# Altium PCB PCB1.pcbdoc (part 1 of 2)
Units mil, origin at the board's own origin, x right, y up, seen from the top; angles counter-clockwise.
Board outline 4280 x 3470 mil, 2 copper layers (Top Layer, Bottom Layer); 101 components, 68 nets, 325 pads, 717 vias.
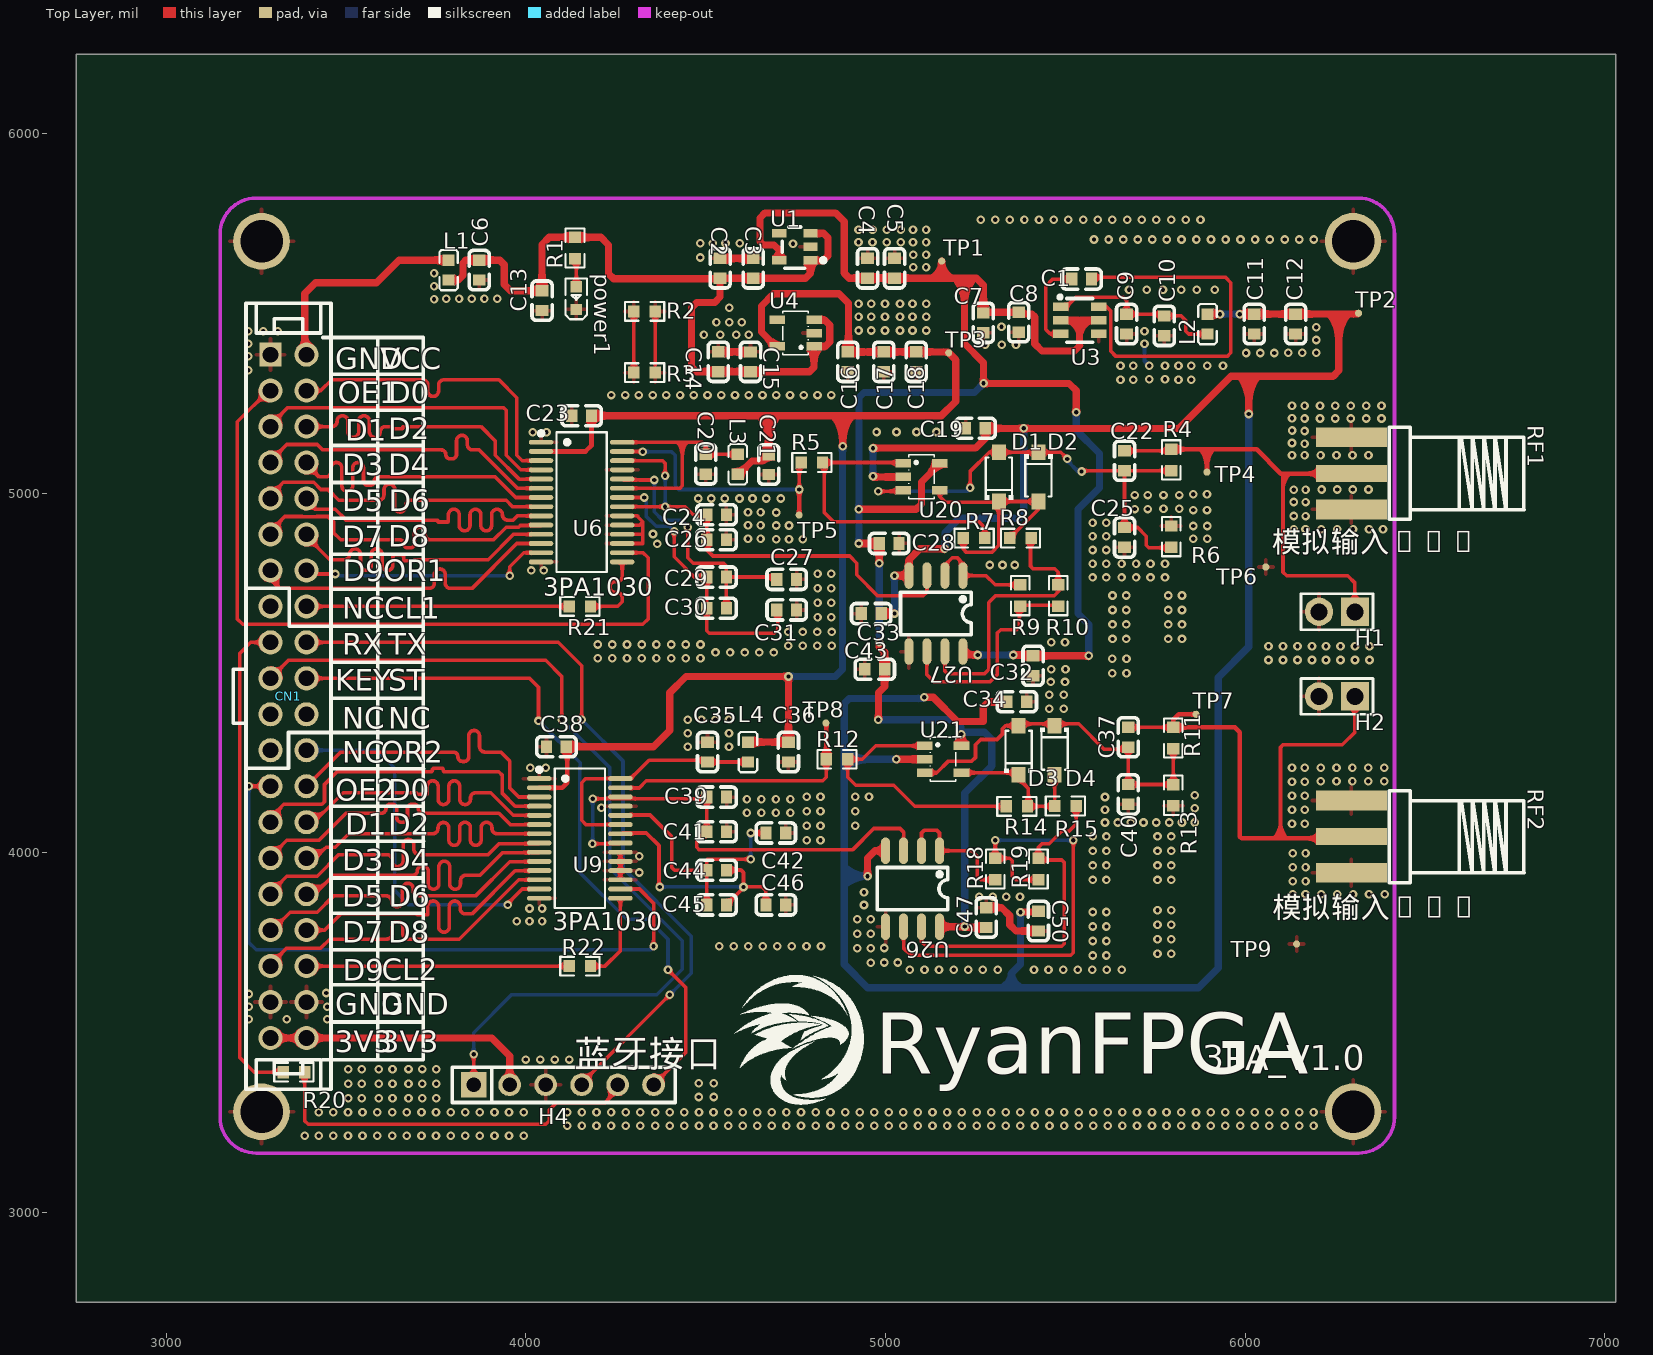
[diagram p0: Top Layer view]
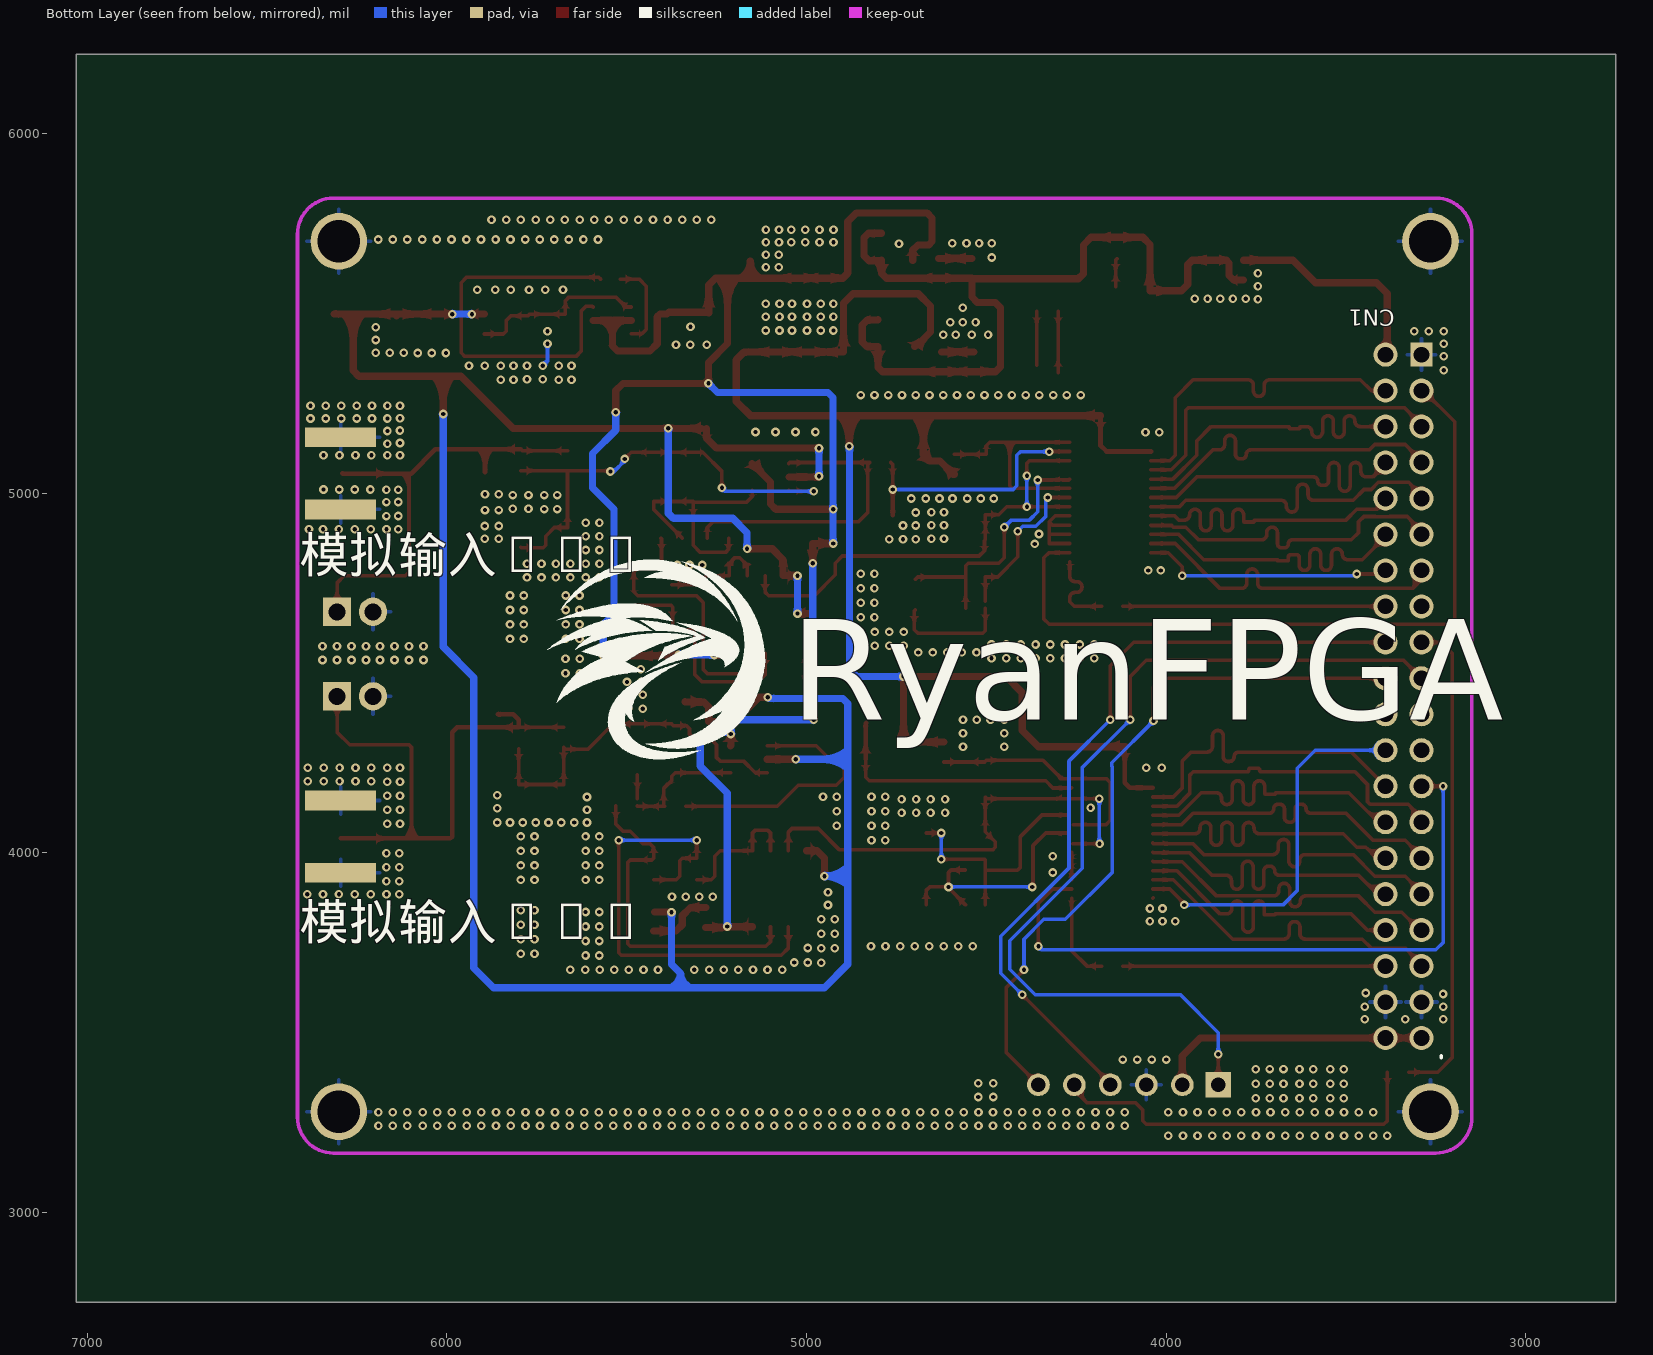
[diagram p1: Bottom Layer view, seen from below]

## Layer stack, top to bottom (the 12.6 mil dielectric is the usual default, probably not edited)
Top Layer: signal copper (thickness not stored)
Dielectric: dielectric 12.6, FR-4, Dk 4.8
Bottom Layer: signal copper (thickness not stored)

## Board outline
7030,2750 2750,2750 2750,6220 7030,6220

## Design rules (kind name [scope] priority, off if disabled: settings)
BoardOutlineClearance copperThickness1oz [All] p0: genericclearance=10 ignorepadtopadclearanceinfootprint=FALSE except(0: Arc-SplitContinuation Track-SplitContinuation SMDPad-SplitContinuation THPad-SplitContinuation Via-SplitContinuation Fill-SplitContinuation Poly-SplitContinuation Region-SplitContinuation Text-SplitContinuation; 6: Track-CutoutEdge SMDPad-CutoutEdge THPad-CutoutEdge Via-CutoutEdge Region-CutoutEdge; 11.8: Track-OutlineEdge SMDPad-OutlineEdge THPad-OutlineEdge Via-OutlineEdge Fill-OutlineEdge Region-OutlineEdge Poly-OutlineEdge Text-OutlineEdge Fill-CutoutEdge)
BoardOutlineClearance copperThickness2oz [All] p0: genericclearance=10 ignorepadtopadclearanceinfootprint=FALSE except(0: Arc-SplitContinuation Track-SplitContinuation SMDPad-SplitContinuation THPad-SplitContinuation Via-SplitContinuation Fill-SplitContinuation Poly-SplitContinuation Region-SplitContinuation Text-SplitContinuation; 6: Track-CutoutEdge SMDPad-CutoutEdge THPad-CutoutEdge Via-CutoutEdge Region-CutoutEdge; 11.8: Track-OutlineEdge SMDPad-OutlineEdge THPad-OutlineEdge Via-OutlineEdge Fill-OutlineEdge Region-OutlineEdge Poly-OutlineEdge Text-OutlineEdge Fill-CutoutEdge)
Clearance copperThickness1oz [(InNet('$1N10336') OR InNet('$1N10331') OR InNet('VCC_5V') OR InNet('AGND') OR InNet('VCC+') OR InNet('$1N10485') OR InNet('VCC-') OR InNet('VCC') OR InNet('$1N3540') OR InNet('$1N1392') OR InNet('$1N17421') OR InNet('$1N3888') OR InNet('$1N3734') OR InNet('$1N12630') OR InNet('$1N12612') OR InNet('$1N17460') OR InNet('$1N12628') OR InNet('$1N12635') OR InNet('$1N12634') OR InNet('$1N2309') OR InNet('$1N12618') OR InNet('VCC_IN') OR InNet('$1N11129') OR InNet('$1N3290') OR InNet('$1N3284') OR InNet('$1N2656') OR InNet('$1N12627') OR InNet('$1N12626') OR InNet('$1N12621') OR InNet('AD2_D0') OR InNet('AD2_CLK') OR InNet('AD2_D2') OR InNet('AD2_D1') OR InNet('AD2_D4') OR InNet('AD2_D3') OR InNet('AD2_D6') OR InNet('AD2_D5') OR InNet('AD2_D8') OR InNet('AD2_D7') OR InNet('AD2_OE') OR InNet('AD2_D9') OR InNet('AD1_OE') OR InNet('AD2_OTR') OR InNet('AD1_D9') OR InNet('AD1_OTR') OR InNet('AD1_D7') OR InNet('AD1_D8') OR InNet('AD1_D5') OR InNet('AD1_D6') OR InNet('AD1_D3') OR InNet('AD1_D4') OR InNet('AD1_D1') OR InNet('AD1_D2') OR InNet('AD1_CLK') OR InNet('AD1_D0') OR InNet('3V3') OR InNet('RX') OR InNet('TX') OR InNet('$1N58701') OR InNet('STATE') OR InNet('KEY') OR InNet('$1N81228') OR InNet('$1N81279') OR InNet('$1N81237') OR InNet('$1N80652') OR InNet('$1N80519') OR InNet('$1N4080') OR InNet('$1N84264'))] p1: gap=7 ignorepadtopadclearanceinfootprint=FALSE except(4: Track-Track; 6: Track-SMDPad SMDPad-SMDPad Track-THPad SMDPad-THPad THPad-THPad Track-Via SMDPad-Via THPad-Via Via-Via SMDPad-Fill THPad-Fill Via-Fill Fill-Fill Track-Region SMDPad-Region THPad-Region Via-Region Region-Region Track-Poly SMDPad-Poly THPad-Poly Via-Poly Fill-Poly Region-Poly Poly-Poly Track-Text SMDPad-Text THPad-Text Via-Text Fill-Text Region-Text Poly-Text Text-Text; 6.9: Track-Hole SMDPad-Hole THPad-Hole Via-Hole Fill-Hole Region-Hole Poly-Hole Text-Hole Sheet-Hole; 11.8: Track-Fill Fill-Region Track-Sheet SMDPad-Sheet THPad-Sheet Via-Sheet Fill-Sheet Region-Sheet Poly-Sheet Text-Sheet)
Clearance copperThickness2oz [All] p1: gap=7 ignorepadtopadclearanceinfootprint=FALSE except(6: Track-SMDPad SMDPad-SMDPad Track-THPad SMDPad-THPad THPad-THPad Track-Via SMDPad-Via THPad-Via Via-Via SMDPad-Fill THPad-Fill Via-Fill Fill-Fill Track-Region SMDPad-Region THPad-Region Via-Region Region-Region Track-Poly SMDPad-Poly THPad-Poly Via-Poly Fill-Poly Region-Poly Poly-Poly Track-Text SMDPad-Text THPad-Text Via-Text Fill-Text Region-Text Poly-Text Text-Text; 6.9: Track-Hole SMDPad-Hole THPad-Hole Via-Hole Fill-Hole Region-Hole Poly-Hole Text-Hole Sheet-Hole; 8: Track-Track; 11.8: Track-Fill Fill-Region Track-Sheet SMDPad-Sheet THPad-Sheet Via-Sheet Fill-Sheet Region-Sheet Poly-Sheet Text-Sheet)
DiffPairsRouting differentialPair [All] p1: maxuncoupledlength=10 minlimit=6 maxlimit=6 mostfreqgap=6 toplayer_minwidth=5 toplayer_prefwidth=10 toplayer_maxwidth=100 bottomlayer_minwidth=5 bottomlayer_prefwidth=10 bottomlayer_maxwidth=100
PasteMaskExpansion pasteMaskExpansion [All] p1: expansion=0
PlaneConnect innerPlane [All] p1: planeconnectstyle=Relief reliefexpansion=20 reliefentries=4 reliefconductorwidth=10 reliefairgap=10
PolygonConnect copperRegion [All] p1: connectstyle=Relief reliefentries=4 reliefconductorwidth=10 polygonreliefangle="90 Angle" airgapwidth=10
RoutingVias viaSize [All] p1: viastyle="Through Hole" holewidth=12.0078 minholewidth=11.811 maxholewidth=248.0314 width=24.0158 minwidth=19.685 maxwidth=393.7008
SolderMaskExpansion solderMaskExpansion [All] p1: useseparateexpansions=TRUE expansion=2 expansionbottom=2
Width copperThickness1oz [All] p1: maxlimit=100 minlimit=5 preferedwidth=10
Width copperThickness2oz [All] p1: maxlimit=100 minlimit=8 preferedwidth=10

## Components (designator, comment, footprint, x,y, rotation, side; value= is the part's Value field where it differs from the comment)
C1 "CL10A475KA8NQNC" C0603 5545,5595 r180 top
C2 "CC0603KRX7R9BB104" C0603 4540,5625 r270 top
C3 "CC0603KRX7R9BB104" C0603 4631.94,5624.94 r270 top
C4 "CC0603KRX7R9BB104" C0603 4950,5625 r270 top
C5 "CC0603KRX7R9BB104" C0603 5025,5625 r270 top
C6 "GRM188R60J476ME15D" C0603 3870,5620 r90 top
C7 "GRM188R60J476ME15D" C0603 5271.65,5473.38 r90 top
C8 "CC0603KRX7R9BB104" C0603 5370,5475 r90 top
C9 "CL10A106KP8NNNC" C0603 5670,5470 r90 top
C10 "CL10A475KA8NQNC" C0603 5775,5465 r90 top
C11 "CL10A105KB8NNNC" C0603 6025,5470 r90 top
C12 "GRM188R60J476ME15D" C0603 6140,5470 r90 top
C13 "104" C0603 4045,5535 r90 top
C14 "GRM188R60J476ME15D" C0603 4535,5365 r270 top
C15 "CC0603KRX7R9BB104" C0603 4624.52,5364.94 r270 top
C16 "CC0603KRX7R9BB104" C0603 4895,5365 r90 top
C17 "CL10A106KP8NNNC" C0603 4995,5365 r90 top
C18 "GRM188R60J476ME15D" C0603 5085,5365 r90 top
C19 "CL10A105KB8NNNC" C0603 5250,5180 r0 top
C20 "CC0603KRX7R9BB104" C0603 4500,5080 r270 top
C21 "CL10A105KB8NNNC" C0603 4675,5079.35 r270 top
C22 "CAP_0603" C0603 5664.4,5090 r90 top
C23 "CC0603KRX7R9BB104" C0603 4155,5215 r180 top
C24 "CL10A106KP8NNNC" C0603 4530,4940 r0 top
C25 "CAP_0603" C0603 5664.4,4876.69 r90 top
C26 "CC0603KRX7R9BB104" C0603 4530,4870 r0 top
C27 "CC0603KRX7R9BB104" C0603 4725,4760 r0 top
C28 "CL10A105KB8NNNC" C0603 5010,4860 r180 top
C29 "CC0603KRX7R9BB104" C0603 4530,4766.67 r0 top
C30 "CL10A106KP8NNNC" C0603 4530,4680 r0 top
C31 "CC0603KRX7R9BB104" C0603 4725,4675 r0 top
C32 "CL10A105KB8NNNC" C0603 5410,4520 r270 top
C33 "CL10A105KB8NNNC" C0603 4960,4665 r180 top
C34 "CL10A105KB8NNNC" C0603 5365,4420 r180 top
C35 "CC0603KRX7R9BB104" C0603 4505,4280 r90 top
C36 "CL10A105KB8NNNC" C0603 4730,4280 r270 top
C37 "CAP_0603" C0603 5675,4321.14 r90 top
C38 "CC0603KRX7R9BB104" C0603 4085,4295 r180 top
C39 "CL10A106KP8NNNC" C0603 4530.35,4154.92 r0 top
C40 "CAP_0603" C0603 5675,4162.19 r90 top
C41 "CC0603KRX7R9BB104" C0603 4530.35,4058.28 r0 top
C42 "CC0603KRX7R9BB104" C0603 4695,4055 r0 top
C43 "CL10A105KB8NNNC" C0603 4970,4510 r0 top
C44 "CC0603KRX7R9BB104" C0603 4530.35,3951.64 r180 top
C45 "CL10A106KP8NNNC" C0603 4530,3855 r180 top
C46 "CC0603KRX7R9BB104" C0603 4695,3855 r0 top
C47 "CL10A105KB8NNNC" C0603 5280,3820 r90 top
C50 "CL10A105KB8NNNC" C0603 5425,3810 r270 top
CN1 "2.54-2*20P压线头" HDR-TH_40P-V-H-R2-P2.54 3340,4435 r270 top
D1 "1N4148W_C81598" SOD-123F_L2.7-W1.6-LS3.8-RD 5315,5045 r90 top
D2 "1N4148W_C81598" SOD-123F_L2.7-W1.6-LS3.8-RD 5425,5045 r270 top
D3 "1N4148W_C81598" SOD-123F_L2.7-W1.6-LS3.8-RD 5370,4285 r90 top
D4 "1N4148W_C81598" SOD-123F_L2.7-W1.6-LS3.8-RD 5470,4285 r270 top
H1 "PZ254V-11-02P" HDR-TH_2P-P2.54-V-M 6255,4670 r180 top
H2 "PZ254V-11-02P" HDR-TH_2P-P2.54-V-M 6255,4435 r180 top
H4 "PM254V-11-06-H85" HDR-TH_6P-P2.54-V-F 4105,3355 r0 top
L1 "SDFL1608S100KTF" L0603 3785,5620 r270 top
L2 "0603WAF1200T5E" L0603 5895,5470 r90 top
L3 "0603WAF1200T5E" L0603 4588.81,5080 r270 top
L4 "0603WAF1200T5E" L0603 4617.47,4280 r90 top
power1 "LTST-C193TBKT-5A" LED_0603 4140,5544.07 r90 top
R1 "0603WAF1001T5E" R0603 4136.56,5681.54 r90 top
R2 "0603WAF0000T5E" R0603 4330,5505 r0 top
R3 "0603WAF0000T5E" R0603 4330,5335 r0 top
R4 "0603WAF1802T5E" R0603 5794.12,5092.19 r90 top
R5 "0603WAF220JT5E" R0603 4795,5085 r0 top
R6 "0603WAF2001T5E" R0603 5794.12,4878.88 r90 top
R7 "0603WAF5100T5E" R0603 5246.1,4875 r180 top
R8 "0603WAF5100T5E" R0603 5375,4875 r0 top
R9 "0603WAF1002T5E" R0603 5374.28,4715 r270 top
R10 "0603WAF1002T5E" R0603 5480,4715 r90 top
R11 "0603WAF1802T5E" R0603 5800,4318.95 r90 top
R12 "0603WAF220JT5E" R0603 4865,4260 r0 top
R13 "0603WAF2001T5E" R0603 5800,4160 r270 top
R14 "0603WAF5100T5E" R0603 5365,4129.05 r0 top
R15 "0603WAF5100T5E" R0603 5500,4130 r0 top
R18 "0603WAF1002T5E" R0603 5305,3955 r90 top
R19 "0603WAF1002T5E" R0603 5425,3955 r90 top
R20 "Res_0603" R0603 3355,3390 r180 top
R21 "Res_0603" R0603 4150,4685 r180 top
R22 "Res_0603" R0603 4150,3685 r180 top
RF1 "KH-SMA-KE8-G" CONN-SMD_KH-SMA-KE8-G 6295,5055 r270 top
RF2 "KH-SMA-KE8-G" CONN-SMD_KH-SMA-KE8-G 6295,4045 r270 top
TP1 "Test-Point" Test-Point-0.5mm 5156.17,5644.94 r0 top
TP2 "Test-Point" Test-Point-0.5mm 6315,5500 r0 top
TP3 "Test-Point" Test-Point-0.5mm 5175.48,5389.94 r0 top
TP4 "Test-Point" Test-Point-0.5mm 5893.48,5058.21 r0 top
TP5 "Test-Point" Test-Point-0.5mm 4759.74,4938.84 r0 top
TP6 "Test-Point" Test-Point-0.5mm 6057.22,4794.47 r0 top
TP7 "Test-Point" Test-Point-0.5mm 5863.48,4385.1 r0 top
TP8 "Test-Point" Test-Point-0.5mm 4834.11,4360.73 r0 top
TP9 "Test-Point" Test-Point-0.5mm 6142.85,3746.36 r0 top
U1 "XC6204B282MR_C18212677" SOT-23-5_L2.9-W1.6-P0.95-LS2.8-BR 4747.58,5684.94 r0 top
U3 "SGM3204YN6G/TR" SOT-23-6_L2.9-W1.6-P0.95-LS2.8-BR 5540,5480 r180 top
U4 "HXC6204B332MR" SOT-23-5_L3.0-W1.7-P0.95-LS2.8-BR 4750,5445 r0 top
U6 "3PA1030" TSSOP-28_L9.7-W4.4-P0.65-LS6.4-BL 4155,4975 r270 top
U9 "3PA1030" TSSOP-28_L9.7-W4.4-P0.65-LS6.4-BL 4150,4040 r270 top
U20 "OPA365AIDBVR" SOT-23-5_L3.0-W1.7-P0.95-LS2.8-BR 5100,5045 r180 top
U21 "OPA365AIDBVR" SOT-23-5_L3.0-W1.7-P0.95-LS2.8-BR 5160,4260 r180 top
U26 "TPH2502-SR" SOP-8_L4.9-W3.9-P1.27-LS6.0-BL 5075,3900 r180 top
U27 "TPH2502-SR" SOP-8_L4.9-W3.9-P1.27-LS6.0-BL 5140,4665 r180 top

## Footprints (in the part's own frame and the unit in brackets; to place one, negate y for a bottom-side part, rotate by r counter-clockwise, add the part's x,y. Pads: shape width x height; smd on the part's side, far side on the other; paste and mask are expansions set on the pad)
C0603 [mm]
  rect 0.8x0.9 smd: 1(-0.7,0) 2(0.7,0)
  silkscreen extent -1.39,-0.71 1.39,0.71
CONN-SMD_KH-SMA-KE8-G [mm]
  rect 1.4x5 smd: 1(-2.55,0) 2(2.55,0)
  rect 1.4x5 smd far side: 3(-2.55,0) 4(2.55,0)
  rect 1.2x5 smd: 5(0,0)
  silkscreen extent -3.25,2.67 3.25,12.19
HDR-TH_2P-P2.54-V-M [mm]
  rect 2x2 hole 1.2: 1(-1.27,0)
  round 2 hole 1.2: 2(1.27,0)
  silkscreen extent -2.54,-1.27 2.54,1.27
HDR-TH_6P-P2.54-V-F [mm]
  rect 1.8x1.8 hole 1.02: 1(-6.35,0)
  round 1.6 hole 1.02: 2(-3.81,0) 3(-1.27,0) 4(1.27,0) 5(3.81,0) 6(6.35,0)
  silkscreen extent -7.87,-1.25 7.87,1.25
HDR-TH_40P-V-H-R2-P2.54 [mm]
  rect 1.7x1.524 hole 1.1: 1(-24.13,-1.27)
  round 1.7 hole 1.1: 2(-24.13,1.27) 3(-21.59,-1.27) 4(-21.59,1.27) 5(-19.05,-1.27) 6(-19.05,1.27) 7(-16.51,-1.27) 8(-16.51,1.27) 9(-13.97,-1.27) 10(-13.97,1.27) 11(-11.43,-1.27) 12(-11.43,1.27) 13(-8.89,-1.27) 14(-8.89,1.27) 15(-6.35,-1.27) 16(-6.35,1.27) 17(-3.81,-1.27) 18(-3.81,1.27) 19(-1.27,-1.27) 20(-1.27,1.27) 21(1.27,-1.27) 22(1.27,1.27) 23(3.81,-1.27) 24(3.81,1.27) 25(6.35,-1.27) 26(6.35,1.27) 27(8.89,-1.27) 28(8.89,1.27) 29(11.43,-1.27) 30(11.43,1.27) 31(13.97,-1.27) 32(13.97,1.27) 33(16.51,-1.27) 34(16.51,1.27) 35(19.05,-1.27) 36(19.05,1.27) 37(21.59,-1.27) 38(21.59,1.27) 39(24.13,-1.27) 40(24.13,1.27)
  silkscreen extent -27.75,-3.9 27.75,3
L0603 [mm]
  rect 0.8x0.864 smd: 1(-0.7,0) 2(0.7,0)
  silkscreen extent -1.42,-0.65 1.42,0.65
LED_0603 [mil]
  rect 31.5x31.5 smd: 1(-33.5,-0.4) 2(29.5,-0.2)
  silkscreen extent -61,-30 53,30
R0603 [mil]
  rect 31.75x34.02 smd: 1(-29.66,0) 2(29.66,0)
  silkscreen extent -55,-26 55,26
SOD-123F_L2.7-W1.6-LS3.8-RD [mm]
  rect 1.1x1 smd: 1(-1.735,0) 2(1.735,0)
  silkscreen extent -1.6,-1 1.38,1
SOP-8_L4.9-W3.9-P1.27-LS6.0-BL [mm]
  oval 0.63x1.865 smd: 1(-1.905,-2.682) 2(-0.635,-2.682) 3(0.635,-2.682) 4(1.905,-2.682) 5(1.905,2.682) 6(0.635,2.682) 7(-0.635,2.682) 8(-1.905,2.682)
  silkscreen extent -2.5,-1.5 2.5,1.48
SOT-23-5_L2.9-W1.6-P0.95-LS2.8-BR [mm]
  rect 1x0.6 smd: 1(1.1,-0.95) 2(1.1,0) 3(1.1,0.95) 4(-1.1,0.95) 5(-1.1,-0.95)
  silkscreen extent -0.89,-1.52 2.16,1.4
SOT-23-5_L3.0-W1.7-P0.95-LS2.8-BR [mm]
  rect 1.1x0.6 smd: 1(1.3,-0.95) 2(1.3,0) 3(1.3,0.95) 4(-1.3,0.95) 5(-1.3,-0.95)
  silkscreen extent -0.9,-1.55 0.9,1.55
SOT-23-6_L2.9-W1.6-P0.95-LS2.8-BR [mm]
  rect 1.1x0.6 smd: 1(1.35,-0.95) 2(1.35,0) 3(1.35,0.95) 4(-1.35,0.95) 5(-1.35,0) 6(-1.35,-0.95)
  silkscreen extent -0.9,-1.78 1.52,1.55
Test-Point-0.5mm [mm]
  round 0.5 smd: 1(0,0)
TSSOP-28_L9.7-W4.4-P0.65-LS6.4-BL [mil]
  oval 13.5x68.17 smd: 1(-166.34,-112.82) 2(-140.75,-112.82) 3(-115.16,-112.82) 4(-89.57,-112.82) 5(-63.98,-112.82) 6(-38.39,-112.82) 7(-12.79,-112.82) 8(12.8,-112.82) 9(38.39,-112.82) 10(63.98,-112.82) 11(89.57,-112.82) 12(115.16,-112.82) 13(140.75,-112.82) 14(166.34,-112.82) 15(166.34,112.82) 16(140.75,112.82) 17(115.16,112.82) 18(89.57,112.82) 19(63.98,112.82) 20(38.39,112.82) 21(12.8,112.82) 22(-12.79,112.82) 23(-38.39,112.82) 24(-63.98,112.82) 25(-89.57,112.82) 26(-115.16,112.82) 27(-140.75,112.82) 28(-166.34,112.82)
  silkscreen extent -197,-119 194,70

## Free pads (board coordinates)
  round 157.48 hole 118.11: 1(3265,3280) 1(3265,5700) 1(6300,3280) 1(6300,5700)

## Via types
v1: diameter 24, hole 12, Top Layer to Bottom Layer, 717 vias

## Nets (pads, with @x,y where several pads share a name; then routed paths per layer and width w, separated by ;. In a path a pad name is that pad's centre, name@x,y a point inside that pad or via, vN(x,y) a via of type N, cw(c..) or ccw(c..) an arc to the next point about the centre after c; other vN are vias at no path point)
3V3: CN1.39 CN1.40 H4.2 | length 765.7
  Top Layer w20: CN1.39@3290,3485 CN1.40@3390,3485 3905,3485 3955,3435 H4.2@3955,3355
$1N1392: C22.2 H1.1 R4.2 RF1.5 TP4.1 | length 1288.8
  Top Layer w10: C22.2@5664.4,5117.56 5789.83,5117.56 R4.2@5794.12,5121.85 ; 6099.19,5054.19 6105,5048.38 6105,4780 6115,4770 6285,4770 6305,4750 H1.1@6305,4670
  Top Layer w13: R4.2@5794.12,5121.85 5894.34,5121.85 ; TP4.1@5893.48,5058.21 5893.48,5121 5894.34,5121.85 ; RF1.5@6290,5055.01 6289.19,5054.19 6099.19,5054.19 6031.53,5121.85 5894.34,5121.85
$1N2309: D1.1 D2.2 R7.2 R8.1 U20.4 | length 696.5
  Top Layer w10: U20.4@5151.19,5007.6 5151.19,4990 5166.19,4975 5313.31,4975 D1.1@5315,4976.69 ; R7.2@5216.44,4875 5216.44,4843.56 5225,4835 5295,4835 5315,4855 D1.1@5315,4976.69 ; R8.1@5345.34,4875 5425,4954.66 D2.2@5425,4976.69 D1.1@5315,4976.69
$1N2656: R8.2 R10.2 U27.7 | length 807.9
  Top Layer w10: U27.7@5165,4574.39 5165,4505 5172.07,4497.93 5275,4497.93 5286.46,4509.39 5286.46,4695.61 5305.5,4714.65 5469.05,4714.65 5480,4725.6 R10.2@5480,4744.66 5480,4780 5470,4790 5410,4790 5402.93,4797.07 5402.93,4873.27 R8.2@5404.66,4875
$1N3284: R5.1 TP5.1 U6.27 | length 709.1
  Top Layer w10: U6.27@4267.82,5115.75 v1@4315,5115.75 ; v1(4760,5010) 4760,5079.66 R5.1@4765.34,5085
  Top Layer w13: TP5.1@4759.74,4938.84 4760,4938.84 v1(4760,5010)
  Bottom Layer w10: v1(4325,5115) 4405,5115 4415,5105 4415,5020 4425,5010 4745,5010
$1N3290: R5.2 R7.1 U20.1 | length 859.3
  Top Layer w10: U20.1@5048.81,5082.4 5046.22,5085 R5.2@4824.66,5085 4830,5079.66 4830,4945 4855,4920 5260,4920 5275.76,4904.24 R7.1@5275.76,4875
$1N3540: C20.1 L3.1 U6.23 U6.28 | length 640.7
  Top Layer w10: U6.23@4267.82,5013.39 4428.39,5013.39 4435,5020 4435,5139.98 4433.64,5141.34 ; U6.28@4267.82,5141.34 4433.64,5141.34 ; L3.1@4588.81,5107.56 C20.1@4500,5107.56 4500,5131.34 4490,5141.34 4433.64,5141.34
$1N3734: C29.1 C30.1 C31.1 U6.22 | length 785.4
  Top Layer w10: U6.22@4267.82,4987.79 v1(4329.05,4987.79) ; v1(4412.07,4894.18) 4412.07,4822.93 4468.33,4766.67 C29.1@4502.44,4766.67 4502.44,4700 ; C30.1@4502.44,4680 4502.44,4617.56 4510,4610 4690,4610 4700,4620 4700,4672.44 C31.1@4697.44,4675
  Bottom Layer w10: v1(4329.05,4987.79) 4335,4981.84 4335,4935 4362.5,4907.5 4398.75,4907.5 v1(4412.07,4894.18)
$1N3888: C27.1 C29.2 C30.2 U6.24 | length 744.9
  Top Layer w10: U6.24@4267.82,5038.98 4270.43,5036.37 4287.62,5036.37 4288.19,5036.95 4315.37,5036.95 4315.95,5036.37 v1(4357.03,5036.37) ; v1(4450,4905) 4450,4820 4465,4805 4550,4805 4557.07,4797.93 4557.07,4767.16 C29.2@4557.56,4766.67 ; C30.2@4557.56,4680 C29.2@4557.56,4766.67 ; C27.1@4697.44,4760 4690.77,4766.67 C29.2@4557.56,4766.67
  Bottom Layer w10: v1(4357.03,5036.37) 4357.03,4947.97 4380,4925 4430,4925 v1@4445,4910
$1N4080: R21.1 U6.15 | length 246.7
  Top Layer w10: R21.1@4179.66,4685 4255,4685 4267.82,4697.82 4267.82,4708.93 ccw(c4252.82,4708.93) 4252.82,4723.93 4248.75,4723.93 cw(c4248.75,4738.93) 4248.75,4753.93 4252.82,4753.93 ccw(c4252.82,4768.93) 4267.82,4768.93 U6.15@4267.82,4808.66
$1N10331: C1.1 U3.6 | length 1085.4
  Top Layer w10: C1.1@5572.56,5595 5577.56,5600 5945,5600 5960,5585 5960,5390 5950,5380 5640.79,5380 5625.79,5395 5625.79,5506.35 5612.93,5519.21 5594.96,5519.21 U3.6@5593.15,5517.4
$1N10336: C1.2 U3.3 | length 247.7
  Top Layer w10: U3.3@5486.85,5442.6 5457.4,5442.6 5445,5455 5445,5575 5465,5595 C1.2@5517.44,5595
$1N10485: C9.2 C10.2 L2.1 U3.1 | length 501.6
  Top Layer w10: U3.1@5486.85,5517.4 5502.4,5517.4 5530,5545 5660,5545 5670,5535 C9.2@5670,5497.56 5770,5497.56 C10.2@5775,5492.56 5822.44,5492.56 5835,5480 5835,5450 5842.56,5442.44 L2.1@5895,5442.44
$1N11129: power1.2 R1.1 | length 79.8
  Top Layer w10: R1.1@4136.56,5651.88 4140.2,5648.24 power1.2@4140.2,5573.57
$1N12612: C37.2 H2.1 R11.2 RF2.5 TP7.1 | length 1585.5
  Top Layer w10: C37.2@5675,4348.7 5799.91,4348.7 R11.2@5800,4348.61 ; 6097.42,4040.01 6097.93,4040.51 6097.93,4292.93 6105,4300 6270,4300 6305,4335 6305,4425 H2.1@6315,4435
  Top Layer w13: TP7.1@5858.39,4385 5815,4385 5800,4370 R11.2@5800,4348.61 5971.39,4348.61 5985,4335 5985,4045.01 5990,4040.01 6097.42,4040.01 RF2.5@6295,4040.01
$1N12618: D3.1 D4.2 R14.2 R15.1 U21.4 | length 404
  Top Layer w10: U21.4@5211.19,4222.6 5364.1,4222.6 D3.1@5370,4216.69 5375,4211.69 5375,4200 5397.25,4177.75 5397.25,4131.46 R14.2@5394.84,4129.05 ; R14.2@5394.66,4129.05 R14.2@5394.84,4129.05 ; 5470,4150 D4.2@5470,4216.69 ; R15.1@5470.34,4130 5469.39,4129.05 R14.2@5394.84,4129.05
$1N12621: R15.2 R19.2 U26.7 | length 962.1
  Top Layer w10: U26.7@5100,3794.39 5100,3752.85 5112.85,3740 5490,3740 5497.07,3747.07 5497.07,3972.93 5490,3980 5429.66,3980 R19.2@5425,3984.66 5425,4015 5435,4025 5455,4025 5490,4060 5510,4060 5530,4080 5530,4129.66 R15.2@5529.66,4130
$1N12626: R12.1 TP8.1 U9.27 | length 736.3
  Top Layer w10: U9.27@4262.82,4180.75 4263.57,4180 4315,4180 4335,4200 4825,4200 4835.34,4210.34 R12.1@4835.34,4260
  Top Layer w13: TP8.1@4834.11,4360.73 4835.34,4359.5 R12.1@4835.34,4260
$1N12627: R12.2 R14.1 U21.1 | length 753.7
  Top Layer w10: U21.1@5108.81,4297.4 4972.4,4297.4 4935,4260 R12.2@4894.66,4260 4894.66,4210.34 4917.5,4187.5 5022.5,4187.5 5080.95,4129.05 R14.1@5335.34,4129.05
$1N12628: C39.1 C41.1 U9.21 U9.26 U26.3 | length 1320.4
  Top Layer w10: v1(4185,4025) U9.21@4260.02,4025 ; v1@4195,4150.16 4498.03,4150.16 C39.1@4502.79,4154.92 C41.1@4502.79,4058.28 4475,4030.49 4475,4015 4482.07,4007.93 4907.93,4007.93 4967.5,4067.5 5040,4067.5 5050,4057.5 U26.3@5050,4005.61
  Bottom Layer w10: v1(4185,4025) 4185.85,4025.85 v1(4185.85,4150.16)
$1N12630: C35.1 L4.1 U9.23 U9.28 | length 703
  Top Layer w10: U9.23@4257.82,4078.39 4166.61,4078.39 4155,4090 4155,4195 4166.34,4206.34 4291.34,4206.34 4342.44,4257.44 4500,4257.44 C35.1@4505,4252.44 L4.1@4617.47,4252.44
$1N12634: C44.1 C45.1 C46.1 U9.22 | length 729.7
  Top Layer w10: U9.22@4270.03,4055 4335,4055 4370,4020 4370,3907.07 v1(4372.07,3905) ; C45.1@4557.56,3855 4605,3902.44 v1(4605,3905) ; C44.1@4557.91,3951.64 4558.34,3952.07 4597.93,3952.07 4605,3945 v1(4605,3905) ; C46.1@4667.44,3855 4667.44,3895 4657.44,3905 v1(4605,3905)
  Bottom Layer w10: v1(4372.07,3905) v1(4605,3905)
$1N12635: C42.1 C44.2 C45.2 U9.24 | length 710.8
  Top Layer w10: U9.24@4268.85,4105 4345,4105 4405,4045 4405,3960 4413.36,3951.64 C44.2@4502.79,3951.64 ; C45.2@4502.44,3855 4502.79,3855.35 C44.2@4502.79,3951.64 ; v1(4625,3982.07) 4504.86,3982.07 4502.79,3980 C44.2@4502.79,3951.64 ; v1(4625,4055.01) C42.1@4667.44,4055
  Bottom Layer w10: v1(4625,3982.07) v1(4625,4055.01)
$1N17421: C22.1 C25.2 D1.2 D2.1 R4.1 R6.1 U20.3 | length 1297.7
  Top Layer w10: v1(4980,5005) 5046.22,5005 U20.3@5048.81,5007.6 ; v1(5235,5015) 5235,5060 5288.31,5113.31 D1.2@5315,5113.31 D2.1@5425,5113.31 5486.69,5113.31 v1(5505,5095) ; v1(5545,5060) 5547.44,5062.44 C22.1@5664.4,5062.44 ; R6.1@5794.12,4849.22 5792.83,4847.93 5732.07,4847.93 5725,4855 5725,4880 5700.76,4904.24 C25.2@5664.4,4904.24 C22.1@5664.4,5062.44 ; R4.1@5794.12,5062.53 5794.03,5062.44 C22.1@5664.4,5062.44
  Bottom Layer w10: v1(4980,5005) 5225,5005 v1(5235,5015) ; v1(5505,5095) 5505,5090 v1@5535,5060
$1N17460: C37.1 C40.2 D3.2 D4.1 R11.1 R13.1 U21.3 | length 1011.7
  Top Layer w10: U21.3@5108.81,4222.6 5142.6,4222.6 5175,4255 5240,4255 5250,4265 5250,4300 5265,4315 5310,4315 5325,4330 5325,4345 5333.31,4353.31 D3.2@5370,4353.31 5375,4358.31 5536.69,4358.31 5607.07,4287.93 5669.35,4287.93 C37.1@5675,4293.58 C40.2@5675,4189.75 5799.91,4189.75 R13.1@5800,4189.66 R11.1@5800,4289.29
$1N58701: CN1.17 R20.2 | length 1359.3
  Top Layer w10: CN1.17@3290,4585 3235,4585 3205,4555 3205,3430 3245,3390 R20.2@3325.34,3390
$1N80519: R18.1 U26.1 U26.2 | length 375.4
  Top Layer w10: U26.2@5100,4005.61 5100,4055 5107.07,4062.07 5142.93,4062.07 5150,4055 U26.1@5150,4005.61 5239.39,4005.61 5255,3990 5255,3935 5265,3925 5304.66,3925 R18.1@5305,3925.34
$1N80652: R18.2 R19.1 U26.6 | length 1292.5
  Top Layer w10: U26.6@5050,3794.39 5050,3735 5070,3715 5515,3715 5522.07,3722.07 v1(5522.07,4035) ; v1(5305,4035) R18.2@5305,3984.66 5345,3984.66 5352.07,3977.59 5352.07,3935 5361.73,3925.34 R19.1@5425,3925.34
  Bottom Layer w10: v1(5305,4035) v1(5522.07,4035)
$1N81228: C24.1 C26.1 U6.21 U6.26 U27.3 | length 1318.7
  Top Layer w10: U6.21@4267.82,4962.2 4386.55,4962.2 v1(4387.02,4961.74) 4443.26,4961.74 4465,4940 C24.1@4502.44,4940 C26.1@4502.44,4870 4505,4867.44 4505,4840 4520,4825 4900,4825 4920,4805 4920,4772.68 4977.68,4715 5105,4715 5115,4725 U27.3@5115,4770.61 ; U6.26@4267.82,5090.16 4304.93,5090.16 4305.39,5089.7 4380.28,5089.72 4387.02,5082.98 v1(4387.02,5048.6)
  Bottom Layer w10: v1(4387.02,4961.74) v1(4387.02,5048.6)
$1N81237: R9.1 U27.1 U27.2 | length 298.3
  Top Layer w10: U27.2@5165,4770.61 5165,4800 5185,4820 5200,4820 5215,4805 U27.1@5215,4770.61 5279.39,4770.61 5305,4745 5373.94,4745 R9.1@5374.28,4744.66
$1N81279: R9.2 R10.1 U27.6 | length 618.6
  Top Layer w10: U27.6@5115,4554.39 5115,4495 5135,4475 5290,4475 5310,4495 5310,4610 5320,4620 5365,4620 5372.07,4627.07 5372.07,4683.13 R9.2@5374.28,4685.34 5376.63,4687.68 R10.1@5477.66,4687.68
$1N84264: R22.1 U9.15 | length 246.7
  Top Layer w10: R22.1@4179.66,3685 4220,3685 4262.82,3727.82 U9.15@4262.82,3873.66
AD1_CLK: CN1.16 R21.2 | length 730.3
  Top Layer w10: CN1.16@3390,4685 R21.2@4120.34,4685
AD1_D0: CN1.4 U6.3 | length 923.4
  Top Layer w10: CN1.4@3385,5285 3430,5285 3460,5315 3712.24,5315 cw(c3712.24,5300) 3727.24,5300 3727.24,5283.67 ccw(c3742.24,5283.67) 3757.24,5283.67 3757.24,5300 cw(c3772.24,5300) 3772.24,5315 3925,5315 3975,5265 3975,5105 3989.84,5090.16 U6.3@4042.18,5090.16
AD1_D1: CN1.5 U6.4 | length 923.4
  Top Layer w10: CN1.5@3285,5185 3337.07,5237.07 3937.93,5237.07 3945,5230 3945,5105 3985.43,5064.57 U6.4@4042.18,5064.57
AD1_D2: CN1.6 U6.5 | length 923.3
  Top Layer w10: CN1.6@3385,5185 3460,5185 ccw(c3460,5200) 3475,5200 cw(c3490,5200) 3505,5200 3505,5170 ccw(c3520,5170) 3535,5170 3535,5200 cw(c3550,5200) 3565,5200 3565,5170 ccw(c3580,5170) 3595,5170 cw(c3610,5170) 3610,5185 3625,5185 cw(c3625,5182.12) 3627.88,5182.12 ccw(c3630.76,5182.12) 3630.76,5179.24 3655,5179.24 ccw(c3655,5182.12) 3657.88,5182.12 cw(c3660.76,5182.12) 3660.76,5185 3875,5185 3915,5145 3915,5105 3981.02,5038.98 U6.5@4042.18,5038.98
AD1_D3: CN1.7 U6.6 | length 923.4
  Top Layer w10: CN1.7@3285,5085 3335,5135 3420,5135 3435,5120 3764.85,5120 cw(c3764.85,5107.68) 3777.17,5107.68 ccw(c3789.49,5107.68) 3789.49,5095.37 3794.85,5095.37 ccw(c3794.85,5107.68) 3807.17,5107.68 3807.17,5145.5 cw(c3822.17,5145.5) 3837.17,5145.5 3837.17,5135 ccw(c3852.17,5135) 3852.17,5120 3870,5120 3976.61,5013.39 U6.6@4042.18,5013.39
AD1_D4: CN1.8 U6.7 | length 923.8
  Top Layer w10: CN1.8@3385,5085 3425,5045 3443.43,5045 ccw(c3443.43,5060) 3458.43,5060 3458.43,5070 cw(c3473.43,5070) 3488.43,5070 3488.43,5020 ccw(c3503.43,5020) 3518.43,5020 3518.43,5070 cw(c3533.43,5070) 3548.43,5070 3548.43,5033.4 ccw(c3560.03,5033.4) 3560.03,5021.8 3566.83,5021.8 ccw(c3566.83,5033.4) 3578.43,5033.4 cw(c3590.03,5033.4) 3590.03,5045 3915,5045 3972.21,4987.79 U6.7@4042.18,4987.79
AD1_D5: CN1.9 U6.8 | length 923.4
  Top Layer w10: CN1.9@3285,4985 3285,4990 3325,5030 3410,5030 3430,5010 3450,5010 3480,4980 3590.49,4980 ccw(c3590.49,4995) 3605.49,4995 3605.49,5010 cw(c3620.49,5010) 3635.49,5010 3635.49,4962.39 ccw(c3650.49,4962.39) 3665.49,4962.39 3665.49,4965 cw(c3680.49,4965) 3680.49,4980 3945,4980 3962.8,4962.2 U6.8@4042.18,4962.2
AD1_D6: CN1.10 U6.9 | length 923.4
  Top Layer w10: CN1.10@3385,4985 3415,4955 3470,4955 3500,4925 3751.95,4925 cw(c3751.95,4922.26) 3754.69,4922.26 ccw(c3757.42,4922.26) 3757.42,4919.53 3781.95,4919.53 ccw(c3781.95,4922.26) 3784.69,4922.26 3784.69,4940 cw(c3799.69,4940) 3814.69,4940 3814.69,4910 ccw(c3829.69,4910) 3844.69,4910 3844.69,4940 cw(c3859.69,4940) 3874.69,4940 3874.69,4910 ccw(c3889.69,4910) 3904.69,4910 3904.69,4940 cw(c3919.69,4940) 3934.69,4940 ccw(c3949.69,4940) 3949.69,4925 3965,4925 3976.61,4936.61 U6.9@4042.18,4936.61
AD1_D7: CN1.11 U6.10 | length 923.4
  Top Layer w10: CN1.11@3285,4885 3285,4890 3330,4935 3377.82,4935 3378.17,4934.65 3418.43,4934.65 3418.77,4935 3450,4935 3465,4920 3465,4890 3485,4870 3649.15,4870 cw(c3649.15,4858.9) 3660.25,4858.9 ccw(c3671.36,4858.9) 3671.36,4847.8 3679.15,4847.8 ccw(c3679.15,4858.9) 3690.25,4858.9 3690.25,4890 cw(c3705.25,4890) 3720.25,4890 3720.25,4885 ccw(c3735.25,4885) 3735.25,4870 3910,4870 3945,4905 3980,4905 3985,4910 4041.16,4910 U6.10@4042.18,4911.02
AD1_D8: CN1.12 U6.11 | length 923.4
  Top Layer w10: CN1.12@3385,4885 3455,4815 3495.2,4815 ccw(c3495.2,4830) 3510.2,4830 cw(c3525.2,4830) 3540.2,4830 3540.2,4800 ccw(c3555.2,4800) 3570.2,4800 3570.2,4830 cw(c3585.2,4830) 3600.2,4830 3600.2,4800 ccw(c3615.2,4800) 3630.2,4800 3630.2,4821.76 cw(c3636.95,4821.76) 3636.95,4828.51 3653.44,4828.51 cw(c3653.44,4821.76) 3660.2,4821.76 3660.2,4813.22 ccw(c3661.97,4813.22) 3661.97,4811.45 3688.42,4811.45 ccw(c3688.42,4813.22) 3690.2,4813.22 cw(c3691.97,4813.22) 3691.97,4815 3895,4815 3965.43,4885.43 U6.11@4042.18,4885.43
AD1_D9: CN1.13 U6.12 | length 923.4
  Top Layer w10: CN1.13@3285,4785 3285,4765 3315,4735 3730.66,4735 ccw(c3730.66,4750) 3745.66,4750 3745.66,4773.93 cw(c3760.66,4773.93) 3775.66,4773.93 3775.66,4750 ccw(c3790.66,4750) 3790.66,4735 3850.16,4735 3975,4859.84 U6.12@4042.18,4859.84
AD1_OE: CN1.3 U6.16 | length 2073.6
  Top Layer w10: CN1.3@3285,5285 3197.93,5197.93 3197.93,4650 3212.93,4635 4325,4635 4340,4650 4340,4820 4325.75,4834.25 U6.16@4267.82,4834.25
AD1_OTR: CN1.14 U6.13 | length 704.6
  Top Layer w10: CN1.14@3385,4785 3395,4775 v1(3470,4775) ; v1(3955,4770) 3955,4795 3994.25,4834.25 U6.13@4042.18,4834.25
  Bottom Layer w10: v1(3470,4775) 3475,4770 v1(3955,4770)
AD2_CLK: CN1.36 R22.2 | length 730.3
  Top Layer w10: CN1.36@3390,3685 R22.2@4120.34,3685
AD2_D0: CN1.26 U9.3 | length 923.4
  Top Layer w10: CN1.26@3385,4185 CN1.26@3390,4185 3485,4280 3797.98,4280 cw(c3797.98,4266.91) 3811.08,4266.91 ccw(c3824.17,4266.91) 3824.17,4253.81 3827.98,4253.81 ccw(c3827.98,4266.91) 3841.08,4266.91 3841.08,4325 cw(c3856.08,4325) 3871.08,4325 3871.08,4295 ccw(c3886.08,4295) 3886.08,4280 3930,4280 3955,4255 3955,4180 3979.84,4155.16 U9.3@4037.18,4155.16
AD2_D1: CN1.27 U9.4 | length 923.4
  Top Layer w10: CN1.27@3285,4085 3285,4092.93 3327.07,4135 3432.93,4135 3440,4142.07 3440,4190 3475,4225 3735.14,4225 ccw(c3735.14,4230.08) 3740.22,4230.08 cw(c3745.3,4230.08) 3745.3,4235.16 3765.14,4235.16 cw(c3765.14,4230.08) 3770.22,4230.08 ccw(c3775.3,4230.08) 3775.3,4225 3924.78,4225 3934.78,4215 3934.78,4164.78 3970,4129.57 U9.4@4037.18,4129.57
AD2_D2: CN1.28 U9.5 | length 923.4
  Top Layer w10: CN1.28@3385,4085 3410,4085 3491.99,4166.99 3694.05,4166.99 cw(c3694.05,4165.12) 3695.92,4165.12 ccw(c3697.78,4165.12) 3697.78,4163.26 3724.05,4163.26 ccw(c3724.05,4165.12) 3725.92,4165.12 3725.92,4185 cw(c3740.92,4185) 3755.92,4185 3755.92,4148.98 ccw(c3770.92,4148.98) 3785.92,4148.98 3785.92,4185 cw(c3800.92,4185) 3815.92,4185 3815.92,4148.98 ccw(c3830.92,4148.98) 3845.92,4148.98 3845.92,4151.99 cw(c3860.92,4151.99) 3860.92,4166.99 3901.99,4166.99 3965,4103.98 U9.5@4037.18,4103.98
AD2_D3: CN1.29 U9.6 | length 923.1
  Top Layer w10: CN1.29@3285,3985 3335,4035 3425,4035 3500,4110 3598.61,4110 ccw(c3598.61,4122.38) 3610.99,4122.38 cw(c3623.37,4122.38) 3623.37,4134.76 3628.61,4134.76 cw(c3628.61,4122.38) 3640.99,4122.38 3640.99,4097.62 ccw(c3653.37,4097.62) 3653.37,4085.24 3658.61,4085.24 ccw(c3658.61,4097.62) 3670.99,4097.62 3670.99,4122.38 cw(c3683.37,4122.38) 3683.37,4134.76 3688.61,4134.76 cw(c3688.61,4122.38) 3700.99,4122.38 ccw(c3713.37,4122.38) 3713.37,4110 3925,4110 3956.61,4078.39 U9.6@4037.18,4078.39
AD2_D4: CN1.30 U9.7 | length 923.4
  Top Layer w10: CN1.30@3385,3985 3415,3985 3445,4015 3470,4015 3507.79,4052.79 3740.67,4052.79 ccw(c3740.67,4067.79) 3755.67,4067.79 3755.67,4069.13 cw(c3770.67,4069.13) 3785.67,4069.13 3785.67,4035.58 ccw(c3800.67,4035.58) 3815.67,4035.58 3815.67,4070 cw(c3830.67,4070) 3845.67,4070 3845.67,4035.58 ccw(c3860.67,4035.58) 3875.67,4035.58 3875.67,4070 cw(c3890.67,4070) 3905.67,4070 3905.67,4067.79 ccw(c3920.67,4067.79) 3920.67,4052.79 U9.7@4037.18,4052.79
AD2_D5: CN1.31 U9.8 | length 923.4
  Top Layer w10: CN1.31@3285,3885 3335,3935 3420,3935 3480,3995 3613.5,3995 cw(c3613.5,3980) 3628.5,3980 3628.5,3976.46 ccw(c3643.5,3976.46) 3658.5,3976.46 3658.5,4021.93 cw(c3673.5,4021.93) 3688.5,4021.93 3688.5,4010 ccw(c3703.5,4010) 3703.5,3995 3895,3995 3925,4025 4034.97,4025 U9.8@4037.18,4027.2
AD2_D6: CN1.32 U9.9 | length 923.4
  Top Layer w10: CN1.32@3385,3885 3412.5,3885 3465,3937.5 3685.64,3937.5 ccw(c3685.64,3950.1) 3698.24,3950.1 cw(c3710.85,3950.1) 3710.85,3962.71 3715.64,3962.71 cw(c3715.64,3950.1) 3728.24,3950.1 3728.24,3913.54 ccw(c3743.24,3913.54) 3758.24,3913.54 3758.24,3961.46 cw(c3773.24,3961.46) 3788.24,3961.46 3788.24,3913.54 ccw(c3803.24,3913.54) 3818.24,3913.54 3818.24,3922.5 cw(c3833.24,3922.5) 3833.24,3937.5 3872.5,3937.5 3935,4000 4035.57,4000 U9.9@4037.18,4001.61
AD2_D7: CN1.33 U9.10 | length 923.4
  Top Layer w10: CN1.33@3285,3785 3295,3785 3345,3835 3420,3835 3465,3880 3611.76,3880 cw(c3611.76,3865) 3626.76,3865 3626.76,3864.64 ccw(c3641.76,3864.64) 3656.76,3864.64 3656.76,3900 cw(c3671.76,3900) 3686.76,3900 3686.76,3895 ccw(c3701.76,3895) 3701.76,3880 3860,3880 3955,3975 4036.16,3975 U9.10@4037.18,3976.02
AD2_D8: CN1.34 U9.11 | length 923.4
  Top Layer w10: CN1.34@3385,3785 3440,3785 3485,3830 3696.3,3830 cw(c3696.3,3829.06) 3697.24,3829.06 ccw(c3698.19,3829.06) 3698.19,3828.12 3726.3,3828.12 ccw(c3726.3,3829.06) 3727.24,3829.06 3727.24,3850.98 cw(c3742.24,3850.98) 3757.24,3850.98 3757.24,3794.36 ccw(c3772.24,3794.36) 3787.24,3794.36 3787.24,3850.98 cw(c3802.24,3850.98) 3817.24,3850.98 3817.24,3845 ccw(c3832.24,3845) 3832.24,3830 3850,3830 3970,3950 4036.74,3950 U9.11@4037.18,3950.43
AD2_D9: CN1.35 U9.12 | length 923.4
  Top Layer w10: CN1.35@3285,3685 3335,3735 3430,3735 3455,3760 3612.88,3760 ccw(c3612.88,3775) 3627.88,3775 3627.88,3793.83 cw(c3642.88,3793.83) 3657.88,3793.83 3657.88,3775 ccw(c3672.88,3775) 3672.88,3760 3815,3760 3979.84,3924.84 U9.12@4037.18,3924.84
AD2_OE: CN1.25 U9.16 | length 1855.9
  Top Layer w10: v1(3230,4185) CN1.25@3285,4185 ; U9.16@4262.82,3899.25 4315.75,3899.25 4355,3860 v1(4355,3740)
  Bottom Layer w10: v1(3230,4185) 3230,3750 3250,3730 4345,3730 v1(4355,3740)
AD2_OTR: CN1.24 U9.13 | length 1038.4
  Top Layer w10: v1@3955.38,3864.62 3990,3899.25 U9.13@4037.18,3899.25
  Bottom Layer w10: CN1.24@3385,4285 3585,4285 3635,4235 3635,3895 3675,3855 v1(3950,3855)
